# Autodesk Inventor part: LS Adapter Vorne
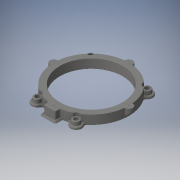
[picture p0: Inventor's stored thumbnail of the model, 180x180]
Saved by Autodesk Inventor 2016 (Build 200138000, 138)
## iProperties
Created: 2015-12
Part Number: LS Adapter Vorne
Material: PC/ABS-Kunststoff
Document SubType Name: Modeling
Designer: Stefan Hagemann
Density: 0.357273 g/cm^3
Appearance: Grau
Author: Stefan Hagemann
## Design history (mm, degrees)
sketch "Skizze1"
  geometry: L1 (-171.6, 0)-(28.6, 0) reference; L2 (0, -206.956)-(0, 201.326) reference; L3 (0, 71.5)-(0, -71.5); A1 r 71.5 centre (0, 0) between (0, 71.5) and (0, -71.5); 1 further point
  constraints: 4 point on line, 2 end point, 2 point on circle, 1 centre point, 1 vertical
  dimensions: "d2" = 71.5 radius of A1
extrude "Extrusion1" new body sketch "Skizze1" distance "d4" = 17; taper "d5" = 0 deg
sketch "Skizze2"
  geometry: L1 (0, -71.5)-(0, 71.5) reference; C1 r 10.5 at (54, 52.766); C2 r 10.5 at (37, -65.812); A1 r 71.5 centre (0, 0) between (0, -71.5) and (0, 71.5) reference; 1 further point
  constraints: 2 centre point
  dimensions: "d8" = 21 diameter of C1; "d9" = 21 diameter of C2; "d10" = 37 distance from line of L1 C2.centre; "d11" = 54 distance from line of L1 C1.centre; "d92" = 75.5 distance of A1.centre C1.centre; "d93" = 75.5 distance of A1.centre C2.centre
extrude "Extrusion2" join sketch "Skizze2" distance "d12" = 4; taper "d13" = 0 deg
extrude "Extrusion3" join sketch "Skizze2" distance "d14" = 4; taper "d15" = 0 deg
sketch "Skizze4"
  geometry: C1 r 7 at (-54, 52.766); 2 further points
  constraints: 1 centre point, 1 coincident
  dimensions: "d16" = 14 diameter of C1
extrude "Extrusion5" cut sketch "Skizze4" stored distance "d19" = 7; taper "d20" = 0 deg
sketch "Skizze5"
  geometry: C1 r 7 at (-37, -65.812); 2 further points
  constraints: 1 centre point, 1 coincident
  dimensions: "d21" = 14 diameter of C1
extrude "Extrusion6" cut sketch "Skizze5" stored distance "d22" = 7; taper "d23" = 0 deg
extrude "Extrusion7" join sketch "Skizze5" distance "d24" = 7; taper "d25" = 0 deg
extrude "Extrusion8" join sketch "Skizze4" distance "d26" = 7; taper "d27" = 0 deg
sketch "Skizze6"
  geometry: L1 (-15, -69.909)-(0, -69.909); L2 (0, -69.909)-(0, -83.909); L3 (0, -83.909)-(-15, -83.909); L4 (-15, -83.909)-(-15, -69.909); L5 (0, -123.858)-(0, 104.06) reference; A1 r 71.5 centre (0, 0) between (0, 71.5) and (0, -71.5) reference; 1 further point
  constraints: 8 end point, 2 parallel, 1 horizontal, 1 perpendicular, 1 point on circle, 1 point on line
  dimensions: "d28" = 15 distance of L2.end L3.end; "d29" = 14 distance between parallel lines of L3 L1
extrude "Extrusion9" join sketch "Skizze6" distance "d30" = 3; taper "d31" = 0 deg
sketch "Skizze7"
  geometry: L1 (-11, -79.909)-(0, -79.909); L2 (0, -79.909)-(0, -70.649); L3 (0, -70.649)-(-11, -70.649); L4 (-11, -70.649)-(-11, -79.909); L5 (-15, -69.909)-(-15, -83.909) reference; L6 (0, -83.909)-(0, 71.5) reference; L7 (-15, -83.909)-(0, -83.909) reference; A1 r 71.5 centre (0, 0) between (-26.517, -66.401) and (-15, -69.909) reference; A2 r 71.5 centre (0, 0) between (0, 71.5) and (0, -71.5) reference; 1 further point
  constraints: 8 end point, 2 parallel, 1 horizontal, 1 perpendicular, 1 point on circle, 1 point on line
  dimensions: "d32" = 4 distance between parallel lines of L7 L1; "d33" = 4 distance between parallel lines of L5 L4
extrude "Extrusion10" join sketch "Skizze7" stored distance "d34" = 3; taper "d35" = 0 deg
sketch "Skizze8"
  geometry: C1 r 4 at (-37, -65.812); A1 r 7 centre (-37, -65.812) between (-30.063, -64.873) and (-39.802, -59.397) reference; A2 r 7 centre (-37, -65.812) between (-39.802, -59.397) and (-30.063, -64.873) reference; 2 further points
  constraints: 1 centre point, 1 coincident
  dimensions: "d43" = 8 diameter of C1
extrude "Extrusion11" cut sketch "Skizze8" stored distance "d44" = 3; taper "d45" = 0 deg
sketch "Skizze9"
  geometry: C1 r 4 at (-54, 52.766); A1 r 7 centre (-54, 52.766) between (-54.887, 45.822) and (-47.079, 53.813) reference; A2 r 7 centre (-54, 52.766) between (-54.887, 45.822) and (-47.079, 53.813) reference; A3 r 7 centre (-54, 52.766) between (-47.079, 53.813) and (-54.887, 45.822) reference; 1 further point
  constraints: 1 centre point, 1 coincident
  dimensions: "d46" = 8 diameter of C1
extrude "Extrusion12" cut sketch "Skizze9" stored distance "d47" = 3; taper "d48" = 0 deg
fillet "Rundung3" dims "d51" = 4
chamfer "Fase1" distance "d52" = 2; stored, may be unused: second distance "d53" = 2, angle "d54" = 45 deg
fillet "Rundung4" dims "d55" = 0.5
fillet "Rundung5" dims "d56" = 1
fillet "Rundung6" dims "d57" = 1
fillet "Rundung7" dims "d58" = 4
fillet "Rundung8" dims "d59" = 2
mirror "Spiegeln1"
sketch "Skizze10"
  geometry: L1 (-94.8, 0)-(15.8, 0) reference; C1 r 7.5 at (-71.5, 0); A1 r 71.5 centre (0, 0) between (-54.887, 45.822) and (-39.802, -59.397) reference; A2 r 71.5 centre (0, 0) between (-59.749, 39.273) and (-46.308, -54.478) reference; 1 further point
  constraints: 1 centre point, 1 point on circle, 1 point on line
  dimensions: "d60" = 15 diameter of C1
extrude "Extrusion13" join sketch "Skizze10" distance "d61" = 8; taper "d62" = 0 deg
chamfer "Fase3" distance "d66" = 5.8; stored, may be unused: second distance "d67" = 2, angle "d68" = 52 deg
fillet "Rundung9" dims "d69" = 2
sketch "Skizze12"
  geometry: 2 further points
hole "Bohrung2" sketch "Skizze12" at (-71.5, 0) diameter "d70" = 1.5; stored, may be unused: countersink angle "d74" = 90 deg, drill point angle "d76" = 118 deg; dims "d71" = 6, "d72" = 4, "d73" = 2, "d75" = 9
pattern_circular "Runde Anordnung1" dims "d78" = 180 deg
sketch "Skizze13"
  geometry: 2 further points
hole "Bohrung3" sketch "Skizze13" at (0, -71.5) diameter "d80" = 1.5; stored, may be unused: countersink angle "d84" = 90 deg, drill point angle "d86" = 118 deg; dims "d81" = 6, "d82" = 4, "d83" = 2, "d85" = 9
sketch "Skizze14"
  geometry: C1 r 60 at (0, 0); 1 further point
  constraints: 1 centre point, 1 coincident
  dimensions: "d87" = 120 diameter of C1
extrude "Extrusion14" cut sketch "Skizze14" stored distance "d88" = 4; taper "d89" = 0 deg
fillet "Rundung10" dims "d90" = 2
fillet "Rundung11" dims "d91" = 1
node "Volumenkörper1"
node "Projizierte Kontur1"
node "Projizierte Kontur2"
